(* Logix 5000 project; controller IS2K 1769-L16ER-BB1B rev 20.19; software revision 20.04 *)

TASK MainTask (continuous, watchdog 500 ms) : MainProgram

MODULES
   Local : 1769-L16ER-BB1B (PointIO 0, rev 20.19)
      IS7802 : vendor 678 type 100 code 276 (Ethernet 192.168.0.73, rev 11.1, Output RPI 60 ms)
      Discrete_IO : Embedded (PointIO 1, rev 20.11, Output RPI 20 ms)
END_MODULES

TYPE IS_Cam_Internal :
STRUCT
   Trigger_Cycle : BOOL;
   Trigger_Toggle : BOOL;
   Trigger_Internal : BOOL;
   Trigger_Ack_Internal : BOOL;
   Job_Pass : BOOL;
   Job_Fail : BOOL;
   User_Data_Sent : BOOL;
   User_Data_Ack_Internal : BOOL;
   Cycle_Complete : BOOL;
   String_To_Send : STRING;
   Oneshot : DINT;
   Reset_Completes : BOOL;
   Job_Number : INT;
   Ok_To_Run_Job_Change : BOOL;
   Start_Job_Change : BOOL;
   Running_Job_Change : BOOL;
   Ok_To_Run_Test_Run : BOOL;
   Start_Test_Run : BOOL;
   Running_Test_Run : BOOL;
   Command_Executing : BOOL;
END_STRUCT
END_TYPE

VAR_GLOBAL   (* controller tags *)
   CAM_IS7802 : IS_Cam_Internal := (String_To_Send := 'ABCDEFGHIJKLMNOPQRSTUVWXYZ123456', Job_Number := 1, Ok_To_Run_Job_Change := 1, Ok_To_Run_Test_Run := 1);
   MyBool : BOOL := 1;
   MyFloat : REAL := 173.72978;
   MyINT : DINT := 111963;
END_VAR

PROGRAM MainProgram   (* main routine Cam1 *)

ROUTINE Cam1   (* ladder *)
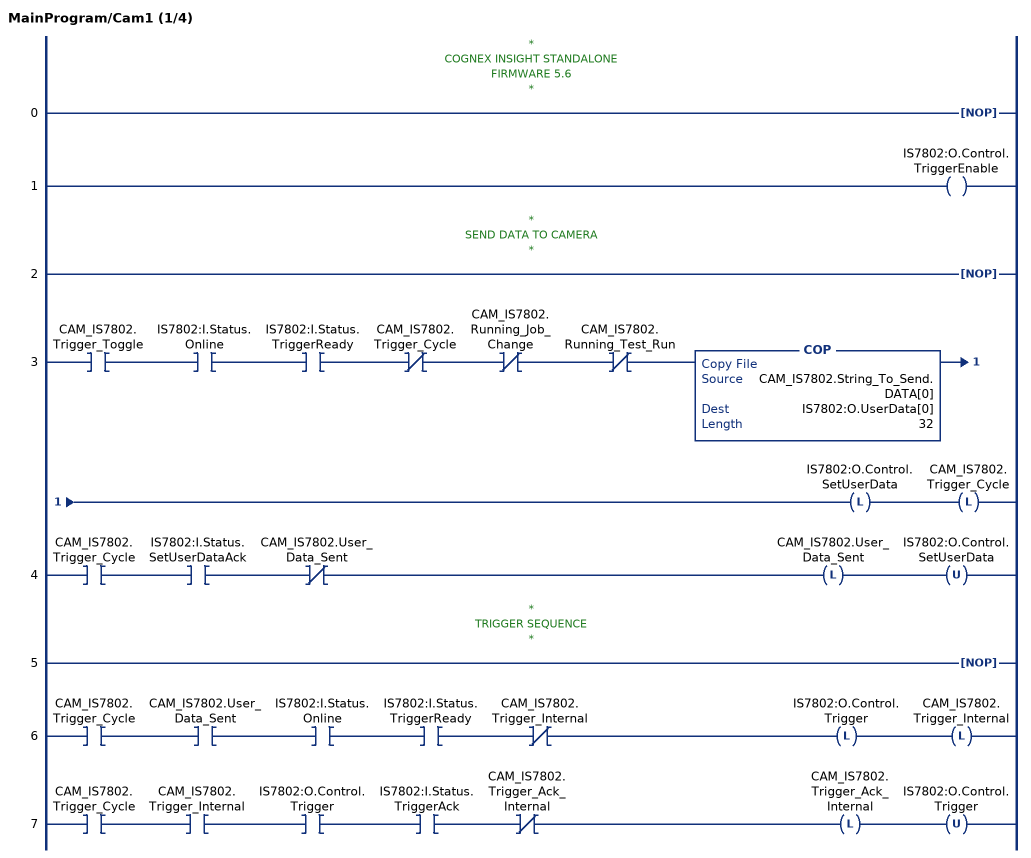
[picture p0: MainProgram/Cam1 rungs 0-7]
   // *
   // COGNEX INSIGHT STANDALONE
   // FIRMWARE 5.6
   // *
   0: NOP();
   1: OTE(IS7802:O.Control.TriggerEnable);
   // *
   // SEND DATA TO CAMERA
   // *
   2: NOP();
   3: XIC(CAM_IS7802.Trigger_Toggle)XIC(IS7802:I.Status.Online)XIC(IS7802:I.Status.TriggerReady)XIO(CAM_IS7802.Trigger_Cycle)XIO(CAM_IS7802.Running_Job_Change)XIO(CAM_IS7802.Running_Test_Run)COP(CAM_IS7802.String_To_Send.DATA[0],IS7802:O.UserData[0],32)OTL(IS7802:O.Control.SetUserData)OTL(CAM_IS7802.Trigger_Cycle);
   4: XIC(CAM_IS7802.Trigger_Cycle)XIC(IS7802:I.Status.SetUserDataAck)XIO(CAM_IS7802.User_Data_Sent)OTL(CAM_IS7802.User_Data_Sent)OTU(IS7802:O.Control.SetUserData);
   // *
   // TRIGGER SEQUENCE
   // *
   5: NOP();
   6: XIC(CAM_IS7802.Trigger_Cycle)XIC(CAM_IS7802.User_Data_Sent)XIC(IS7802:I.Status.Online)XIC(IS7802:I.Status.TriggerReady)XIO(CAM_IS7802.Trigger_Internal)OTL(IS7802:O.Control.Trigger)OTL(CAM_IS7802.Trigger_Internal);
   7: XIC(CAM_IS7802.Trigger_Cycle)XIC(CAM_IS7802.Trigger_Internal)XIC(IS7802:O.Control.Trigger)XIC(IS7802:I.Status.TriggerAck)XIO(CAM_IS7802.Trigger_Ack_Internal)OTL(CAM_IS7802.Trigger_Ack_Internal)OTU(IS7802:O.Control.Trigger);
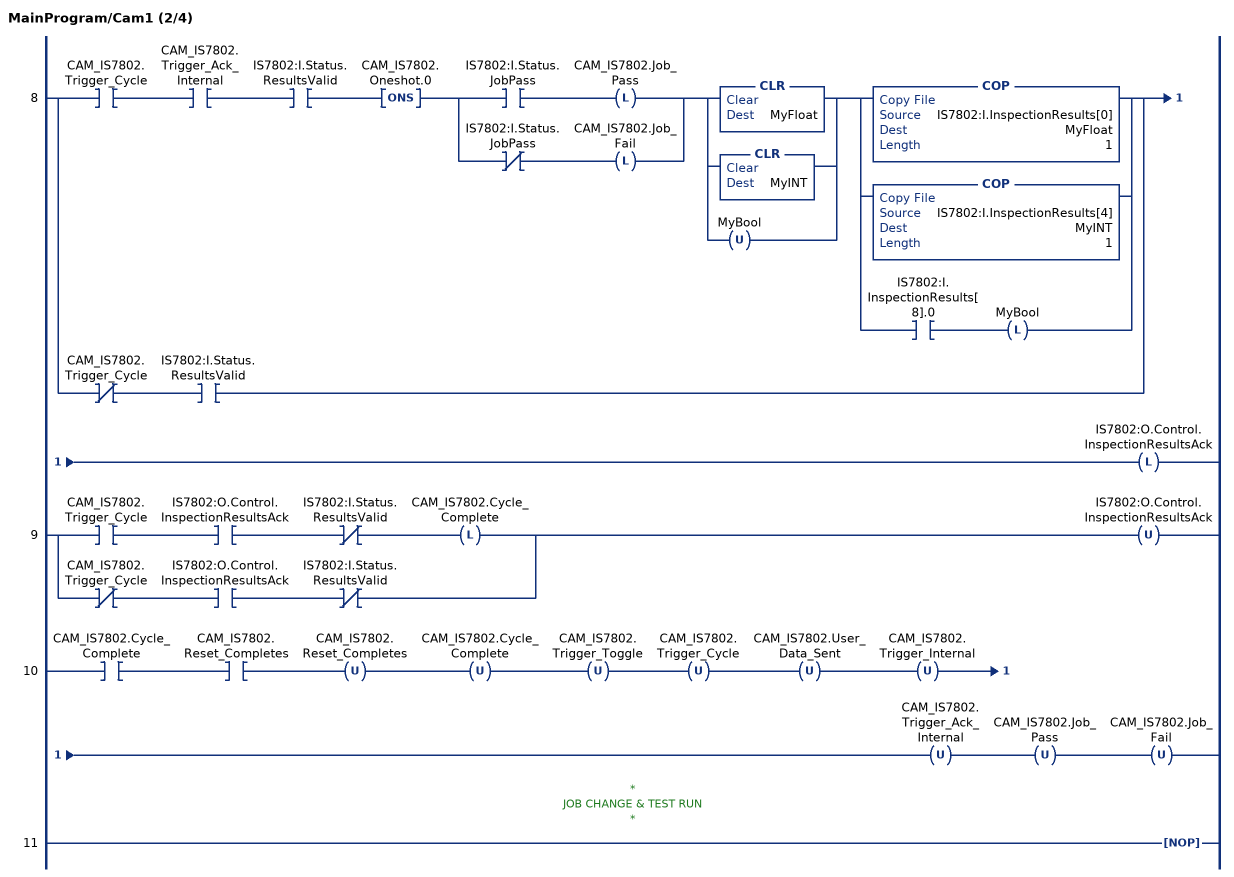
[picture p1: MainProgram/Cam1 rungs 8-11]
   8: [XIC(CAM_IS7802.Trigger_Cycle) XIC(CAM_IS7802.Trigger_Ack_Internal) XIC(IS7802:I.Status.ResultsValid) ONS(CAM_IS7802.Oneshot.0) [XIC(IS7802:I.Status.JobPass) OTL(CAM_IS7802.Job_Pass) ,XIO(IS7802:I.Status.JobPass) OTL(CAM_IS7802.Job_Fail) ] [CLR(MyFloat) ,CLR(MyINT) ,OTU(MyBool) ] [COP(IS7802:I.InspectionResults[0],MyFloat,1) ,COP(IS7802:I.InspectionResults[4],MyINT,1) ,XIC(IS7802:I.InspectionResults[8].0) OTL(MyBool) ] ,XIO(CAM_IS7802.Trigger_Cycle) XIC(IS7802:I.Status.ResultsValid) ]OTL(IS7802:O.Control.InspectionResultsAck);
   9: [XIC(CAM_IS7802.Trigger_Cycle) XIC(IS7802:O.Control.InspectionResultsAck) XIO(IS7802:I.Status.ResultsValid) OTL(CAM_IS7802.Cycle_Complete) ,XIO(CAM_IS7802.Trigger_Cycle) XIC(IS7802:O.Control.InspectionResultsAck) XIO(IS7802:I.Status.ResultsValid) ]OTU(IS7802:O.Control.InspectionResultsAck);
   10: XIC(CAM_IS7802.Cycle_Complete)XIC(CAM_IS7802.Reset_Completes)OTU(CAM_IS7802.Reset_Completes)OTU(CAM_IS7802.Cycle_Complete)OTU(CAM_IS7802.Trigger_Toggle)OTU(CAM_IS7802.Trigger_Cycle)OTU(CAM_IS7802.User_Data_Sent)OTU(CAM_IS7802.Trigger_Internal)OTU(CAM_IS7802.Trigger_Ack_Internal)OTU(CAM_IS7802.Job_Pass)OTU(CAM_IS7802.Job_Fail);
   // *
   // JOB CHANGE & TEST RUN
   // *
   11: NOP();
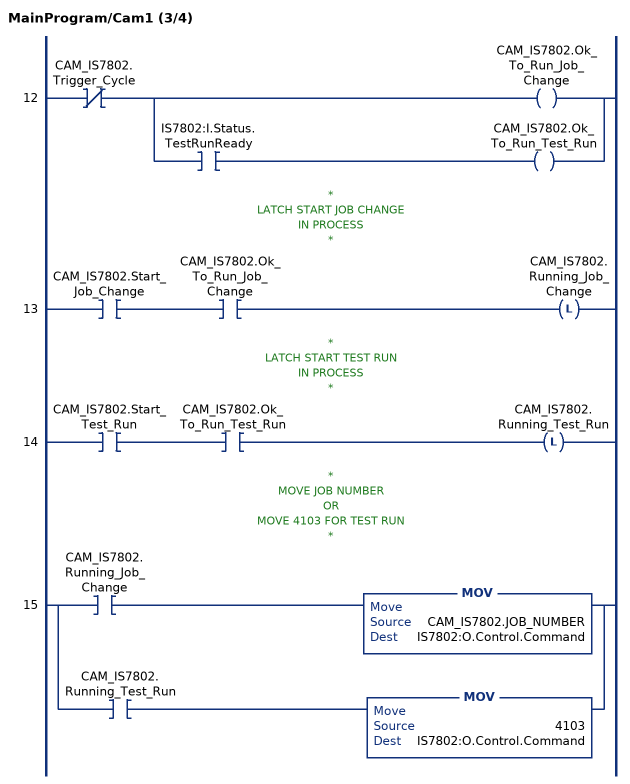
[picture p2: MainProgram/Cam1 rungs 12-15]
   12: XIO(CAM_IS7802.Trigger_Cycle)[OTE(CAM_IS7802.Ok_To_Run_Job_Change) ,XIC(IS7802:I.Status.TestRunReady) OTE(CAM_IS7802.Ok_To_Run_Test_Run) ];
   // *
   // LATCH START JOB CHANGE
   // IN PROCESS
   // *
   13: XIC(CAM_IS7802.Start_Job_Change)XIC(CAM_IS7802.Ok_To_Run_Job_Change)OTL(CAM_IS7802.Running_Job_Change);
   // *
   // LATCH START TEST RUN
   // IN PROCESS
   // *
   14: XIC(CAM_IS7802.Start_Test_Run)XIC(CAM_IS7802.Ok_To_Run_Test_Run)OTL(CAM_IS7802.Running_Test_Run);
   // *
   // MOVE JOB NUMBER
   // OR
   // MOVE 4103 FOR TEST RUN
   // *
   15: [XIC(CAM_IS7802.Running_Job_Change) MOV(CAM_IS7802.JOB_NUMBER,IS7802:O.Control.Command) ,XIC(CAM_IS7802.Running_Test_Run) MOV(4103,IS7802:O.Control.Command) ];
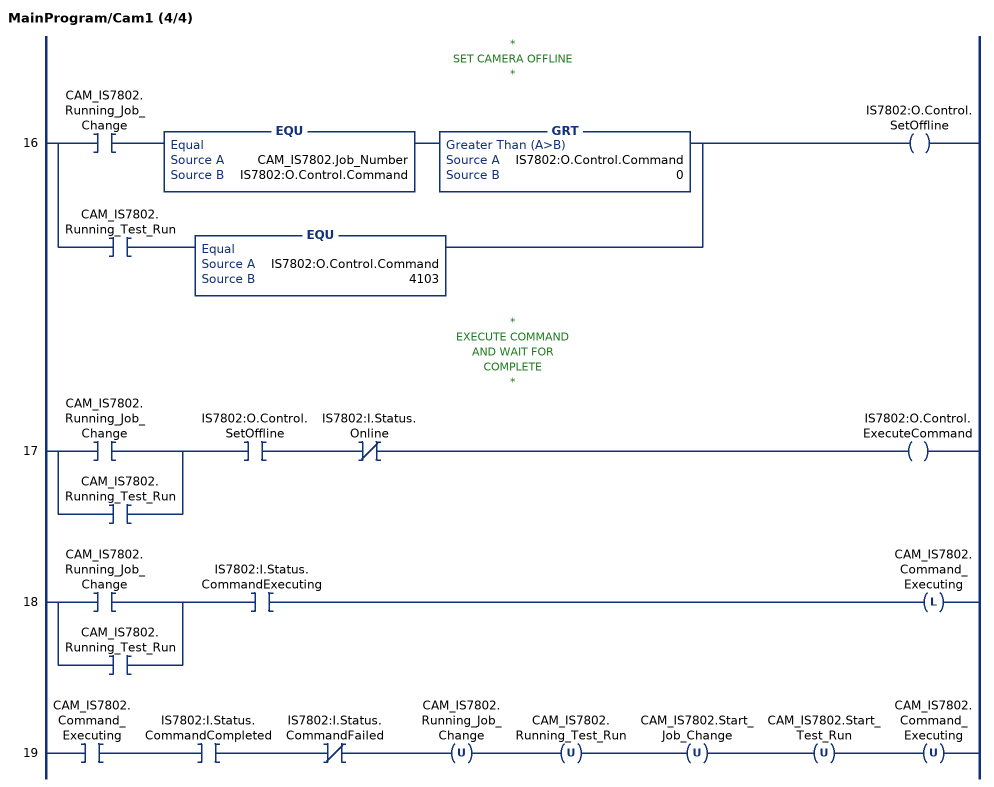
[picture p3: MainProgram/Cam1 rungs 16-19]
   // *
   // SET CAMERA OFFLINE
   // *
   16: [XIC(CAM_IS7802.Running_Job_Change) EQU(CAM_IS7802.Job_Number,IS7802:O.Control.Command) GRT(IS7802:O.Control.Command,0) ,XIC(CAM_IS7802.Running_Test_Run) EQU(IS7802:O.Control.Command,4103) ]OTE(IS7802:O.Control.SetOffline);
   // *
   // EXECUTE COMMAND
   // AND WAIT FOR
   // COMPLETE
   // *
   17: [XIC(CAM_IS7802.Running_Job_Change) ,XIC(CAM_IS7802.Running_Test_Run) ]XIC(IS7802:O.Control.SetOffline)XIO(IS7802:I.Status.Online)OTE(IS7802:O.Control.ExecuteCommand);
   18: [XIC(CAM_IS7802.Running_Job_Change) ,XIC(CAM_IS7802.Running_Test_Run) ]XIC(IS7802:I.Status.CommandExecuting)OTL(CAM_IS7802.Command_Executing);
   19: XIC(CAM_IS7802.Command_Executing)XIC(IS7802:I.Status.CommandCompleted)XIO(IS7802:I.Status.CommandFailed)OTU(CAM_IS7802.Running_Job_Change)OTU(CAM_IS7802.Running_Test_Run)OTU(CAM_IS7802.Start_Job_Change)OTU(CAM_IS7802.Start_Test_Run)OTU(CAM_IS7802.Command_Executing);
END_ROUTINE
END_PROGRAM
